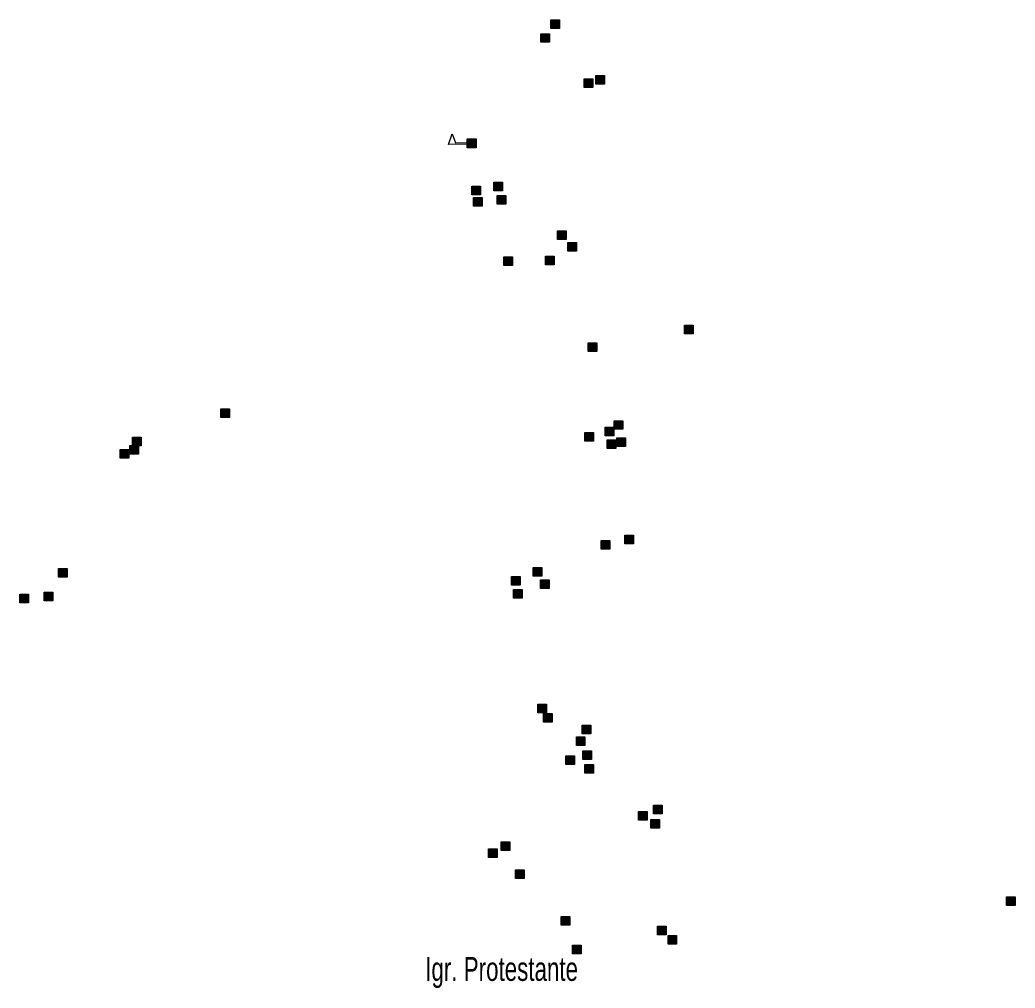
# Model space of a CAD drawing. Extents: x 647.8 to 672.9, y 6929.3 to 6957.3.
# Drawn here: x 668.17 to 671.505, y 6950.108 to 6953.351 of the extents above; entities that cross this region are included whole.
import ezdxf
from ezdxf.enums import TextEntityAlignment as Align

# ---------------------------------------------------------------- set-up
doc = ezdxf.new("R2010")
doc.units = 0
doc.header["$LTSCALE"] = 0.032
doc.layers.add('2', color=7, linetype='Continuous', lineweight=25)
doc.layers.add('4', color=7, linetype='Continuous', lineweight=25)
doc.layers.add('61', color=7, linetype='Continuous')

msp = doc.modelspace()

# ---------------------------------------------------------------- hatches: boundary and pattern name
at = {"layer": '2'}
for points in [[(669.949, 6953.3514), (669.978, 6953.3514), (669.978, 6953.3224), (669.949, 6953.3224)], [(669.916, 6953.3053), (669.945, 6953.3053), (669.945, 6953.2763), (669.916, 6953.2763)], [(670.1003, 6953.1649), (670.1293, 6953.1649), (670.1293, 6953.1359), (670.1003, 6953.1359)], [(670.0608, 6953.1539), (670.0898, 6953.1539), (670.0898, 6953.1249), (670.0608, 6953.1249)], [(669.6848, 6952.7945), (669.7138, 6952.7945), (669.7138, 6952.7655), (669.6848, 6952.7655)], [(669.7581, 6952.8073), (669.7871, 6952.8073), (669.7871, 6952.7783), (669.7581, 6952.7783)], [(669.7691, 6952.7634), (669.7981, 6952.7634), (669.7981, 6952.7344), (669.7691, 6952.7344)], [(669.6901, 6952.7569), (669.7191, 6952.7569), (669.7191, 6952.7279), (669.6901, 6952.7279)], [(669.9709, 6952.645), (669.9999, 6952.645), (669.9999, 6952.616), (669.9709, 6952.616)], [(670.006, 6952.6055), (670.035, 6952.6055), (670.035, 6952.5765), (670.006, 6952.5765)], [(669.9314, 6952.5594), (669.9604, 6952.5594), (669.9604, 6952.5304), (669.9314, 6952.5304)], [(669.791, 6952.5572), (669.82, 6952.5572), (669.82, 6952.5282), (669.791, 6952.5282)], [(670.3965, 6952.3291), (670.4255, 6952.3291), (670.4255, 6952.3001), (670.3965, 6952.3001)], [(670.074, 6952.2698), (670.103, 6952.2698), (670.103, 6952.2408), (670.074, 6952.2408)], [(668.8433, 6952.0482), (668.8723, 6952.0482), (668.8723, 6952.0192), (668.8433, 6952.0192)], [(670.1618, 6952.0088), (670.1908, 6952.0088), (670.1908, 6951.9798), (670.1618, 6951.9798)], [(670.063, 6951.9693), (670.092, 6951.9693), (670.092, 6951.9403), (670.063, 6951.9403)], [(670.131, 6951.9868), (670.16, 6951.9868), (670.16, 6951.9578), (670.131, 6951.9578)], [(668.5383, 6951.9254), (668.5673, 6951.9254), (668.5673, 6951.8964), (668.5383, 6951.8964)], [(668.5471, 6951.9539), (668.5761, 6951.9539), (668.5761, 6951.9249), (668.5471, 6951.9249)], [(670.1376, 6951.9451), (670.1666, 6951.9451), (670.1666, 6951.9161), (670.1376, 6951.9161)], [(670.1705, 6951.9517), (670.1995, 6951.9517), (670.1995, 6951.9227), (670.1705, 6951.9227)], [(668.5054, 6951.9122), (668.5344, 6951.9122), (668.5344, 6951.8832), (668.5054, 6951.8832)], [(670.1969, 6951.6248), (670.2259, 6951.6248), (670.2259, 6951.5958), (670.1969, 6951.5958)], [(670.1179, 6951.6073), (670.1469, 6951.6073), (670.1469, 6951.5783), (670.1179, 6951.5783)], [(668.2992, 6951.513), (668.3282, 6951.513), (668.3282, 6951.484), (668.2992, 6951.484)], [(669.8897, 6951.5173), (669.9187, 6951.5173), (669.9187, 6951.4883), (669.8897, 6951.4883)], [(669.8173, 6951.4866), (669.8463, 6951.4866), (669.8463, 6951.4576), (669.8173, 6951.4576)], [(669.9139, 6951.4757), (669.9429, 6951.4757), (669.9429, 6951.4467), (669.9139, 6951.4467)], [(668.1697, 6951.4274), (668.1987, 6951.4274), (668.1987, 6951.3984), (668.1697, 6951.3984)], [(668.2509, 6951.434), (668.2799, 6951.434), (668.2799, 6951.405), (668.2509, 6951.405)], [(669.8239, 6951.4427), (669.8529, 6951.4427), (669.8529, 6951.4137), (669.8239, 6951.4137)], [(669.9051, 6951.0588), (669.9341, 6951.0588), (669.9341, 6951.0298), (669.9051, 6951.0298)], [(669.9248, 6951.0281), (669.9538, 6951.0281), (669.9538, 6950.9991), (669.9248, 6950.9991)], [(670.0543, 6950.9886), (670.0833, 6950.9886), (670.0833, 6950.9596), (670.0543, 6950.9596)], [(670.0345, 6950.9491), (670.0635, 6950.9491), (670.0635, 6950.9201), (670.0345, 6950.9201)], [(670.0565, 6950.9031), (670.0855, 6950.9031), (670.0855, 6950.8741), (670.0565, 6950.8741)], [(669.9994, 6950.8855), (670.0284, 6950.8855), (670.0284, 6950.8565), (669.9994, 6950.8565)], [(670.063, 6950.857), (670.092, 6950.857), (670.092, 6950.828), (670.063, 6950.828)], [(670.2429, 6950.699), (670.2719, 6950.699), (670.2719, 6950.67), (670.2429, 6950.67)], [(670.2934, 6950.721), (670.3224, 6950.721), (670.3224, 6950.692), (670.2934, 6950.692)], [(670.2846, 6950.6727), (670.3136, 6950.6727), (670.3136, 6950.6437), (670.2846, 6950.6437)], [(669.7822, 6950.5981), (669.8112, 6950.5981), (669.8112, 6950.5691), (669.7822, 6950.5691)], [(669.7405, 6950.574), (669.7695, 6950.574), (669.7695, 6950.545), (669.7405, 6950.545)], [(669.8305, 6950.5038), (669.8595, 6950.5038), (669.8595, 6950.4748), (669.8305, 6950.4748)], [(671.4759, 6950.4138), (671.5049, 6950.4138), (671.5049, 6950.3848), (671.4759, 6950.3848)], [(669.9841, 6950.348), (670.0131, 6950.348), (670.0131, 6950.319), (669.9841, 6950.319)], [(670.3066, 6950.3151), (670.3356, 6950.3151), (670.3356, 6950.2861), (670.3066, 6950.2861)], [(670.3417, 6950.2844), (670.3707, 6950.2844), (670.3707, 6950.2554), (670.3417, 6950.2554)], [(670.0214, 6950.2515), (670.0504, 6950.2515), (670.0504, 6950.2225), (670.0214, 6950.2225)]]:
    msp.add_hatch(color=256, dxfattribs=at).paths.add_polyline_path(points)
at = {"layer": '4'}
msp.add_hatch(color=256, dxfattribs=at).paths.add_polyline_path([(669.6988, 6952.923), (669.6688, 6952.9227), (669.6685, 6952.9527), (669.6985, 6952.953)])

# ---------------------------------------------------------------- linework, layer by layer
at = {"layer": '2'}
for points in [[(669.949, 6953.3514), (669.978, 6953.3514), (669.978, 6953.3224), (669.949, 6953.3224)], [(669.916, 6953.3053), (669.945, 6953.3053), (669.945, 6953.2763), (669.916, 6953.2763)], [(670.1003, 6953.1649), (670.1293, 6953.1649), (670.1293, 6953.1359), (670.1003, 6953.1359)], [(670.0608, 6953.1539), (670.0898, 6953.1539), (670.0898, 6953.1249), (670.0608, 6953.1249)], [(669.6848, 6952.7945), (669.7138, 6952.7945), (669.7138, 6952.7655), (669.6848, 6952.7655)], [(669.7581, 6952.8073), (669.7871, 6952.8073), (669.7871, 6952.7783), (669.7581, 6952.7783)], [(669.7691, 6952.7634), (669.7981, 6952.7634), (669.7981, 6952.7344), (669.7691, 6952.7344)], [(669.6901, 6952.7569), (669.7191, 6952.7569), (669.7191, 6952.7279), (669.6901, 6952.7279)], [(669.9709, 6952.645), (669.9999, 6952.645), (669.9999, 6952.616), (669.9709, 6952.616)], [(670.006, 6952.6055), (670.035, 6952.6055), (670.035, 6952.5765), (670.006, 6952.5765)], [(669.9314, 6952.5594), (669.9604, 6952.5594), (669.9604, 6952.5304), (669.9314, 6952.5304)], [(669.791, 6952.5572), (669.82, 6952.5572), (669.82, 6952.5282), (669.791, 6952.5282)], [(670.3965, 6952.3291), (670.4255, 6952.3291), (670.4255, 6952.3001), (670.3965, 6952.3001)], [(670.074, 6952.2698), (670.103, 6952.2698), (670.103, 6952.2408), (670.074, 6952.2408)], [(668.8433, 6952.0482), (668.8723, 6952.0482), (668.8723, 6952.0192), (668.8433, 6952.0192)], [(670.1618, 6952.0088), (670.1908, 6952.0088), (670.1908, 6951.9798), (670.1618, 6951.9798)], [(670.063, 6951.9693), (670.092, 6951.9693), (670.092, 6951.9403), (670.063, 6951.9403)], [(670.131, 6951.9868), (670.16, 6951.9868), (670.16, 6951.9578), (670.131, 6951.9578)], [(668.5383, 6951.9254), (668.5673, 6951.9254), (668.5673, 6951.8964), (668.5383, 6951.8964)], [(668.5471, 6951.9539), (668.5761, 6951.9539), (668.5761, 6951.9249), (668.5471, 6951.9249)], [(670.1376, 6951.9451), (670.1666, 6951.9451), (670.1666, 6951.9161), (670.1376, 6951.9161)], [(670.1705, 6951.9517), (670.1995, 6951.9517), (670.1995, 6951.9227), (670.1705, 6951.9227)], [(668.5054, 6951.9122), (668.5344, 6951.9122), (668.5344, 6951.8832), (668.5054, 6951.8832)], [(670.1969, 6951.6248), (670.2259, 6951.6248), (670.2259, 6951.5958), (670.1969, 6951.5958)], [(670.1179, 6951.6073), (670.1469, 6951.6073), (670.1469, 6951.5783), (670.1179, 6951.5783)], [(668.2992, 6951.513), (668.3282, 6951.513), (668.3282, 6951.484), (668.2992, 6951.484)], [(669.8897, 6951.5173), (669.9187, 6951.5173), (669.9187, 6951.4883), (669.8897, 6951.4883)], [(669.8173, 6951.4866), (669.8463, 6951.4866), (669.8463, 6951.4576), (669.8173, 6951.4576)], [(669.9139, 6951.4757), (669.9429, 6951.4757), (669.9429, 6951.4467), (669.9139, 6951.4467)], [(668.1697, 6951.4274), (668.1987, 6951.4274), (668.1987, 6951.3984), (668.1697, 6951.3984)], [(668.2509, 6951.434), (668.2799, 6951.434), (668.2799, 6951.405), (668.2509, 6951.405)], [(669.8239, 6951.4427), (669.8529, 6951.4427), (669.8529, 6951.4137), (669.8239, 6951.4137)], [(669.9051, 6951.0588), (669.9341, 6951.0588), (669.9341, 6951.0298), (669.9051, 6951.0298)], [(669.9248, 6951.0281), (669.9538, 6951.0281), (669.9538, 6950.9991), (669.9248, 6950.9991)], [(670.0543, 6950.9886), (670.0833, 6950.9886), (670.0833, 6950.9596), (670.0543, 6950.9596)], [(670.0345, 6950.9491), (670.0635, 6950.9491), (670.0635, 6950.9201), (670.0345, 6950.9201)], [(670.0565, 6950.9031), (670.0855, 6950.9031), (670.0855, 6950.8741), (670.0565, 6950.8741)], [(669.9994, 6950.8855), (670.0284, 6950.8855), (670.0284, 6950.8565), (669.9994, 6950.8565)], [(670.063, 6950.857), (670.092, 6950.857), (670.092, 6950.828), (670.063, 6950.828)], [(670.2429, 6950.699), (670.2719, 6950.699), (670.2719, 6950.67), (670.2429, 6950.67)], [(670.2934, 6950.721), (670.3224, 6950.721), (670.3224, 6950.692), (670.2934, 6950.692)], [(670.2846, 6950.6727), (670.3136, 6950.6727), (670.3136, 6950.6437), (670.2846, 6950.6437)], [(669.7822, 6950.5981), (669.8112, 6950.5981), (669.8112, 6950.5691), (669.7822, 6950.5691)], [(669.7405, 6950.574), (669.7695, 6950.574), (669.7695, 6950.545), (669.7405, 6950.545)], [(669.8305, 6950.5038), (669.8595, 6950.5038), (669.8595, 6950.4748), (669.8305, 6950.4748)], [(671.4759, 6950.4138), (671.5049, 6950.4138), (671.5049, 6950.3848), (671.4759, 6950.3848)], [(669.9841, 6950.348), (670.0131, 6950.348), (670.0131, 6950.319), (669.9841, 6950.319)], [(670.3066, 6950.3151), (670.3356, 6950.3151), (670.3356, 6950.2861), (670.3066, 6950.2861)], [(670.3417, 6950.2844), (670.3707, 6950.2844), (670.3707, 6950.2554), (670.3417, 6950.2554)], [(670.0214, 6950.2515), (670.0504, 6950.2515), (670.0504, 6950.2225), (670.0214, 6950.2225)]]:
    msp.add_lwpolyline(points, close=True, dxfattribs=at)
at = {"layer": '4'}
msp.add_line((669.6686, 6952.9352), (669.6686, 6952.9402), dxfattribs=at)
for points in [[(669.6686, 6952.9352), (669.6062, 6952.9345), (669.6183, 6952.9696), (669.6291, 6952.9397), (669.6686, 6952.9402)], [(669.6988, 6952.923), (669.6688, 6952.9227), (669.6685, 6952.9527), (669.6985, 6952.953)]]:
    msp.add_lwpolyline(points, close=True, dxfattribs=at)

# ---------------------------------------------------------------- texts
at = {"layer": '61', "width": 0.7}
msp.add_text('Igr. Protestante', height=0.08, dxfattribs=at).set_placement((670.0401, 6950.132), align=Align.RIGHT)

doc.saveas('drawing.dxf')
